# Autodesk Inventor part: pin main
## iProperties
Author: Rich
Shininess: 20.0
PropertySet Name: _Private Model Information
Created: 2001-04
Part Number: pin main
Document SubType Name: Modeling
Designer: Rich
Control State: 0
Master: False
Checked Out: False
PropertySet Name: Design Tracking Control
Density: 0.0
Volumn: 0.0
Area: 0.0
PropertySet Name: Model Information
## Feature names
1. Extrusion1
2. Extrusion2
3. Chamfer1
4. Hole1
5. Mirror1
